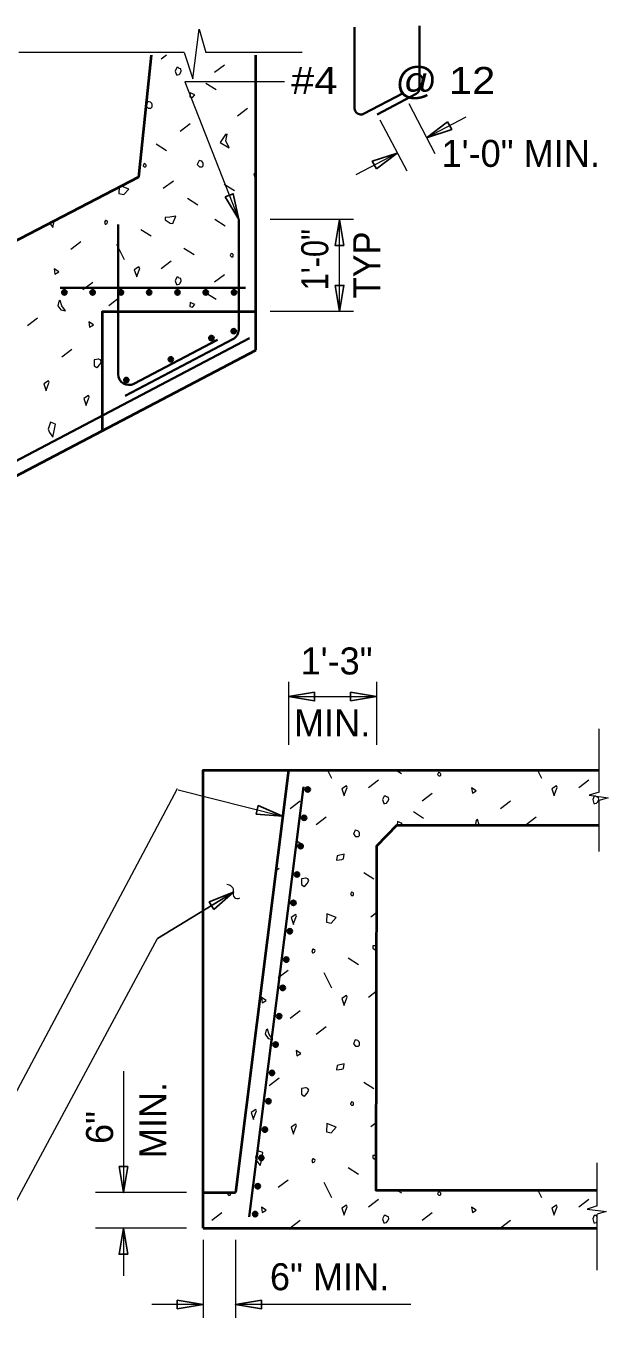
# Model space of a CAD drawing. Extents: x 0 to 22.7, y 0 to 15.6.
# Drawn here: x 6.629 to 8.87, y 5.449 to 10.444 of the extents above; entities that cross this region are included whole.
import ezdxf
from ezdxf.enums import TextEntityAlignment as Align

# ---------------------------------------------------------------- set-up
doc = ezdxf.new("R2010")
doc.units = 0
doc.header["$LTSCALE"] = 0.042
for name, color, linetype, lineweight in [('1', 7, 'Continuous', 13), ('3', 7, 'Continuous', 35), ('4', 7, 'Continuous', 13), ('7', 7, 'Continuous', 13)]:
    doc.layers.add(name, color=color, linetype=linetype, lineweight=lineweight)

msp = doc.modelspace()

# ---------------------------------------------------------------- linework, layer by layer
at = {"layer": '1'}
for p, q in [((7.23859, 10.3412), (6.60214, 10.3412)), ((7.69302, 10.3412), (7.32229, 10.3412)), ((8.83552, 7.49188), (8.83552, 7.73552)), ((8.83552, 7.26333), (8.83552, 7.45979)), ((8.82766, 5.89724), (8.82766, 6.06318)), ((8.82766, 5.64901), (8.82766, 5.86521))]:
    msp.add_line(p, q, dxfattribs=at)
at = {"layer": '1', "lineweight": 40}
for p, q in [((7.11073, 10.33198), (7.06307, 9.8613)), ((7.51385, 9.19516), (7.51385, 10.33198)), ((7.06307, 9.8613), (6.14734, 9.38661)), ((6.14396, 8.47438), (7.51385, 9.19516)), ((7.64047, 7.57573), (7.43552, 5.94859)), ((8.05745, 7.36453), (8.83552, 7.36458)), ((7.31172, 5.94859), (7.43552, 5.94859)), ((7.31172, 5.81099), (8.82734, 5.81099))]:
    msp.add_line(p, q, dxfattribs=at)
at = {"layer": '1'}
for points in [[(7.23859, 10.3412), (7.27115, 10.24057), (7.29661, 10.43167), (7.32229, 10.3412)], [(8.83552, 7.49188), (8.79693, 7.47932), (8.87005, 7.46969), (8.83552, 7.45979)], [(8.82766, 5.89724), (8.78906, 5.88474), (8.86219, 5.8751), (8.82766, 5.86521)]]:
    msp.add_lwpolyline(points, dxfattribs=at)
at = {"layer": '1', "lineweight": 40}
for points in [[(6.92401, 8.88714), (6.92401, 9.34396), (7.51385, 9.34396)], [(7.31172, 5.81099), (7.31172, 7.57661), (8.83552, 7.57661)], [(8.05745, 7.36453), (7.97885, 7.28281), (7.97667, 5.95828), (8.82766, 5.95833)]]:
    msp.add_lwpolyline(points, dxfattribs=at)
at = {"layer": '3'}
for p, q in [((7.89438, 10.43938), (7.89438, 10.12646)), ((8.14411, 10.20302), (8.14411, 10.44417)), ((8.08135, 10.18552), (7.92911, 10.10547)), ((7.98078, 10.10276), (8.13156, 10.18198)), ((7.44818, 9.27396), (7.44818, 9.69792)), ((6.98396, 9.67896), (6.98396, 9.10219)), ((6.76094, 9.43484), (7.475, 9.43484)), ((6.14974, 8.53552), (7.49031, 9.24089)), ((7.01094, 9.0187), (7.42594, 9.23708)), ((7.04505, 9.06531), (7.3662, 9.23427)), ((7.69776, 7.5125), (7.48901, 5.85479))]:
    msp.add_line(p, q, dxfattribs=at)
for centre, radius in [((6.77707, 9.41733), 0.0089), ((6.77707, 9.41733), 0.00593), ((6.77707, 9.41733), 0.00297), ((6.88592, 9.41733), 0.0089), ((6.88592, 9.41733), 0.00593), ((6.88592, 9.41733), 0.00297), ((6.99478, 9.41733), 0.0089), ((6.99478, 9.41733), 0.00593), ((6.99478, 9.41733), 0.00297), ((7.10363, 9.41733), 0.0089), ((7.10363, 9.41733), 0.00593), ((7.10363, 9.41733), 0.00297), ((7.21249, 9.41733), 0.0089), ((7.21249, 9.41733), 0.00593), ((7.21249, 9.41733), 0.00297), ((7.32134, 9.41733), 0.0089), ((7.32134, 9.41733), 0.00593), ((7.32134, 9.41733), 0.00297), ((7.4302, 9.41733), 0.0089), ((7.4302, 9.41733), 0.00593), ((7.4302, 9.41733), 0.00297), ((7.34311, 9.24124), 0.0089), ((7.34311, 9.24124), 0.00593), ((7.34311, 9.24124), 0.00297), ((7.42884, 9.2679), 0.0089), ((7.42884, 9.2679), 0.00593), ((7.42884, 9.2679), 0.00297), ((7.18697, 9.15936), 0.0089), ((7.18697, 9.15936), 0.00593), ((7.18697, 9.15936), 0.00297), ((7.01561, 9.07936), 0.0089), ((7.01561, 9.07936), 0.00593), ((7.01561, 9.07936), 0.00297), ((7.71379, 7.50171), 0.0089), ((7.71379, 7.50171), 0.00593), ((7.71379, 7.50171), 0.00297), ((7.70004, 7.39249), 0.0089), ((7.70004, 7.39249), 0.00593), ((7.70004, 7.39249), 0.00297), ((7.68629, 7.28327), 0.0089), ((7.68629, 7.28327), 0.00593), ((7.68629, 7.28327), 0.00297), ((7.67254, 7.17405), 0.0089), ((7.67254, 7.17405), 0.00593), ((7.67254, 7.17405), 0.00297), ((7.65884, 7.06483), 0.0089), ((7.65884, 7.06483), 0.00593), ((7.65884, 7.06483), 0.00297), ((7.64509, 6.95561), 0.0089), ((7.64509, 6.95561), 0.00593), ((7.64509, 6.95561), 0.00297), ((7.63134, 6.84639), 0.0089), ((7.63134, 6.84639), 0.00593), ((7.63134, 6.84639), 0.00297), ((7.61764, 6.73718), 0.0089), ((7.61764, 6.73718), 0.00593), ((7.61764, 6.73718), 0.00297), ((7.60389, 6.62801), 0.0089), ((7.60389, 6.62801), 0.00593), ((7.60389, 6.62801), 0.00297), ((7.59014, 6.51879), 0.0089), ((7.59014, 6.51879), 0.00593), ((7.59014, 6.51879), 0.00297), ((7.57645, 6.40957), 0.0089), ((7.57645, 6.40957), 0.00593), ((7.57645, 6.40957), 0.00297), ((7.5627, 6.30035), 0.0089), ((7.5627, 6.30035), 0.00593), ((7.5627, 6.30035), 0.00297), ((7.54895, 6.19113), 0.0089), ((7.54895, 6.19113), 0.00593), ((7.54895, 6.19113), 0.00297), ((7.53525, 6.08192), 0.0089), ((7.53525, 6.08192), 0.00593), ((7.53525, 6.08192), 0.00297), ((7.5215, 5.9727), 0.0089), ((7.5215, 5.9727), 0.00593), ((7.5215, 5.9727), 0.00297), ((7.51155, 5.86556), 0.0089), ((7.51155, 5.86556), 0.00593), ((7.51155, 5.86556), 0.00297)]:
    msp.add_circle(centre, radius, dxfattribs=at)
for centre, radius, start, end in [((8.12044, 10.20304), 0.0237, 297.75329, 0), ((7.91807, 10.12645), 0.0237, 180, 297.75192), ((7.91807, 10.12645), 0.0237, 180, 297.75192), ((7.40651, 9.27396), 0.04167, 297.75329, 0), ((7.02563, 9.10218), 0.04167, 180, 297.75192)]:
    msp.add_arc(centre, radius, start, end, dxfattribs=at)
at = {"layer": '4'}
for p, q in [((8.10281, 10.14469), (8.20354, 9.95297)), ((8.32234, 10.0925), (8.17177, 10.01344)), ((7.9913, 10.08271), (8.09484, 9.88563)), ((8.05885, 9.95417), (7.89938, 9.87042)), ((7.89063, 9.69792), (7.56984, 9.69792)), ((7.8363, 9.34396), (7.8363, 9.69792)), ((7.89063, 9.34396), (7.56984, 9.34396)), ((7.64047, 7.91599), (7.64047, 7.67328)), ((7.97885, 7.91599), (7.97885, 7.67328)), ((7.64047, 7.85974), (7.97885, 7.85974)), ((6.36161, 5.9025), (7.21276, 7.50573)), ((7.21495, 7.50063), (7.61646, 7.3987)), ((7.42859, 7.10609), (7.13583, 6.92714)), ((7.13583, 6.92714), (7.42859, 7.10609)), ((6.33057, 5.43), (7.13583, 6.92714)), ((7.00448, 6.41635), (7.00448, 5.94859)), ((7.24781, 5.94859), (6.89677, 5.94859)), ((7.24781, 5.81099), (6.89677, 5.81099)), ((7.00448, 5.81099), (7.00448, 5.62786)), ((7.31172, 5.76641), (7.31172, 5.46568)), ((7.43552, 5.76641), (7.43552, 5.46568)), ((7.31172, 5.51682), (7.11443, 5.51682)), ((8.11146, 5.51682), (7.43552, 5.51682))]:
    msp.add_line(p, q, dxfattribs=at)
msp.add_lwpolyline([(7.62406, 10.22911), (7.2413, 10.22911), (7.44818, 9.69792)], dxfattribs=at)
at = {"layer": '4', "lineweight": 25}
for points in [[(8.25255, 10.07469), (8.26807, 10.04516), (8.17177, 10.01344)], [(7.97807, 9.89292), (7.96255, 9.92245), (8.05885, 9.95417)], [(7.39635, 9.78505), (7.4274, 9.79714), (7.44818, 9.69792)], [(7.85297, 9.59792), (7.81964, 9.59792), (7.8363, 9.69792)], [(7.81964, 9.44396), (7.85297, 9.44396), (7.8363, 9.34396)], [(7.74047, 7.87641), (7.74047, 7.84307), (7.64047, 7.85974)], [(7.87885, 7.84307), (7.87885, 7.87641), (7.97885, 7.85974)], [(7.51542, 7.40714), (7.52365, 7.43948), (7.61646, 7.3987)], [(7.35198, 7.03974), (7.33458, 7.06818), (7.42859, 7.10609)], [(6.98781, 6.04859), (7.02115, 6.04859), (7.00448, 5.94859)], [(7.02115, 5.71099), (6.98781, 5.71099), (7.00448, 5.81099)], [(7.21172, 5.50016), (7.21172, 5.53349), (7.31172, 5.51682)], [(7.53552, 5.53349), (7.53552, 5.50016), (7.43552, 5.51682)]]:
    msp.add_lwpolyline(points, close=True, dxfattribs=at)
at = {"layer": '4'}
for centre, radius, start, end in [((7.4031, 7.10937), 0.0257, 352.67535, 92.38286), ((7.44329, 7.09799), 0.01679, 151.12288, 301.99449)]:
    msp.add_arc(centre, radius, start, end, dxfattribs=at)
at = {"layer": '7'}
for p, q in [((7.17073, 10.33198), (7.14979, 10.31604)), ((7.39406, 10.29339), (7.35557, 10.26406)), ((7.32214, 10.22411), (7.36172, 10.19911)), ((7.48234, 10.12615), (7.44385, 10.09682)), ((7.26141, 10.06635), (7.22292, 10.03708)), ((7.13099, 9.98948), (7.17063, 9.96453)), ((7.19656, 9.84656), (7.15802, 9.81729)), ((7.51385, 9.8776), (7.50656, 9.87281)), ((7.50656, 9.87281), (7.51385, 9.85156)), ((7.39255, 9.83464), (7.43208, 9.80979)), ((7.25167, 9.78), (7.2913, 9.755)), ((7.35661, 9.69943), (7.39615, 9.67438)), ((7.07156, 9.66016), (7.11115, 9.63516)), ((6.84031, 9.6124), (6.80182, 9.58313)), ((6.9776, 9.60354), (7.00693, 9.54469)), ((7.23667, 9.58792), (7.27625, 9.56292)), ((7.18828, 9.5374), (7.14979, 9.50813)), ((6.88698, 9.45589), (6.84849, 9.42656)), ((7.39406, 9.48542), (7.35557, 9.45615)), ((6.98641, 9.39464), (6.94792, 9.36531)), ((7.32214, 9.41615), (7.36172, 9.39115)), ((7.0987, 9.345), (7.09823, 9.34396)), ((7.1024, 9.34396), (7.0987, 9.345)), ((6.67354, 9.31818), (6.63505, 9.28885)), ((6.80557, 9.19724), (6.76708, 9.16792)), ((7.78995, 7.57583), (7.80531, 7.54505)), ((8.05438, 7.57604), (8.07464, 7.56323)), ((8.59844, 7.57646), (8.61411, 7.54505)), ((7.98667, 7.53771), (7.94818, 7.50844)), ((8.79547, 7.53771), (8.75698, 7.50844)), ((7.68536, 7.4562), (7.64688, 7.42693)), ((8.19245, 7.48573), (8.15396, 7.45646)), ((8.49417, 7.4562), (8.45568, 7.42693)), ((7.78479, 7.39495), (7.7463, 7.36568)), ((8.12052, 7.41651), (8.1601, 7.39151)), ((8.59359, 7.39495), (8.5551, 7.36568)), ((8.05943, 7.37859), (8.0588, 7.36453)), ((7.60396, 7.19755), (7.59167, 7.18818)), ((7.92938, 7.18182), (7.96901, 7.15688)), ((7.97844, 7.02635), (7.95641, 7.00964)), ((7.86995, 6.8525), (7.90953, 6.8275)), ((7.6387, 6.80479), (7.60021, 6.77547)), ((7.77599, 6.79589), (7.80531, 6.73708)), ((7.97792, 6.72307), (7.94818, 6.70047)), ((7.68536, 6.64823), (7.64688, 6.61896)), ((7.78479, 6.58698), (7.7463, 6.55771)), ((7.60396, 6.38958), (7.56547, 6.36031)), ((7.92938, 6.37391), (7.96901, 6.34891)), ((7.97708, 6.2174), (7.95641, 6.20167)), ((7.86995, 6.04453), (7.90953, 6.01953)), ((7.6387, 5.99682), (7.60021, 5.96755)), ((7.77599, 5.98797), (7.80531, 5.92911)), ((8.05729, 5.95828), (8.07464, 5.94734)), ((8.59953, 5.95833), (8.61411, 5.92911)), ((7.98667, 5.92182), (7.94818, 5.8925)), ((8.79547, 5.92182), (8.75698, 5.8925)), ((7.38365, 5.86984), (7.34516, 5.84052)), ((8.19245, 5.86984), (8.15396, 5.84052)), ((7.68536, 5.84026), (7.64688, 5.81099)), ((8.49417, 5.84026), (8.45568, 5.81099))]:
    msp.add_line(p, q, dxfattribs=at)
for points in [[(7.2037, 10.27031), (7.20833, 10.25552), (7.2126, 10.25552), (7.21859, 10.25698), (7.22292, 10.2613), (7.22724, 10.27031), (7.22604, 10.27906), (7.21859, 10.28057), (7.21547, 10.28365), (7.20958, 10.28365)], [(7.0987, 10.15292), (7.0913, 10.13677), (7.09995, 10.12776), (7.11052, 10.12776), (7.1149, 10.1325), (7.1149, 10.14109), (7.11344, 10.14536), (7.10885, 10.1501)], [(7.26104, 10.18625), (7.26036, 10.17042), (7.2699, 10.16818), (7.27911, 10.17885)], [(7.39703, 10.02552), (7.37646, 9.99469), (7.41109, 9.97396), (7.39844, 10.00198), (7.40375, 10.02766)], [(7.08396, 9.91344), (7.08026, 9.90536), (7.08458, 9.90083), (7.0899, 9.90083), (7.09203, 9.90323), (7.09203, 9.9075), (7.0913, 9.90969), (7.08901, 9.91203)], [(7.29552, 9.92594), (7.28813, 9.90979), (7.29677, 9.90078), (7.3074, 9.90078), (7.31172, 9.90552), (7.31172, 9.91411), (7.31026, 9.91839), (7.30568, 9.92313)], [(6.93198, 9.68755), (6.93432, 9.68016), (6.93646, 9.68016), (6.93943, 9.68089), (6.94161, 9.68302), (6.94375, 9.68755), (6.94313, 9.69193), (6.93943, 9.69271), (6.93786, 9.69422), (6.93495, 9.69422)], [(7.18339, 9.70776), (7.16573, 9.70625), (7.16573, 9.69745), (7.1849, 9.68422), (7.19526, 9.68271), (7.20557, 9.71073)], [(7.41922, 9.56703), (7.41552, 9.55891), (7.41984, 9.55443), (7.42516, 9.55443), (7.42734, 9.55677), (7.42734, 9.56109), (7.42661, 9.56323), (7.42432, 9.56563)], [(6.73755, 9.50802), (6.74052, 9.48734), (6.75531, 9.49625)], [(7.04641, 9.5037), (7.05552, 9.47708), (7.05552, 9.48), (7.06729, 9.50958), (7.06427, 9.51547)], [(7.2037, 9.46234), (7.20833, 9.4476), (7.2126, 9.4476), (7.21859, 9.44906), (7.22292, 9.45333), (7.22724, 9.46234), (7.22604, 9.47109), (7.21859, 9.4726), (7.21547, 9.47568), (7.20958, 9.47568)], [(6.75552, 9.38266), (6.75229, 9.36604), (6.76328, 9.34984), (6.78172, 9.3462), (6.76698, 9.36573), (6.76068, 9.38594)], [(7.26104, 9.37828), (7.26036, 9.36245), (7.2699, 9.36021), (7.27911, 9.37094)], [(6.87083, 9.30344), (6.87385, 9.28281), (6.88865, 9.29167)], [(6.89214, 9.15698), (6.89214, 9.13469), (6.90224, 9.1275), (6.90531, 9.13036), (6.91401, 9.13927), (6.9199, 9.15109), (6.91563, 9.15698), (6.90969, 9.15984), (6.90682, 9.15984), (6.90104, 9.15823)], [(6.69776, 9.06484), (6.70688, 9.03828), (6.70688, 9.04115), (6.7187, 9.07073), (6.71568, 9.07661)], [(6.85151, 9.00828), (6.86063, 8.98172), (6.86063, 8.98458), (6.8724, 9.01417), (6.86943, 9.02005)], [(6.72365, 8.9174), (6.71469, 8.89083), (6.71927, 8.8776), (6.7325, 8.8599), (6.73833, 8.88349), (6.74281, 8.91005)], [(8.2176, 7.56734), (8.21391, 7.55922), (8.21823, 7.55474), (8.22354, 7.55474), (8.22573, 7.55708), (8.22573, 7.56141), (8.225, 7.56354), (8.22271, 7.56594)], [(7.84479, 7.50401), (7.85391, 7.47745), (7.85391, 7.48031), (7.86568, 7.5099), (7.86266, 7.51578)], [(8.34474, 7.50833), (8.34771, 7.48766), (8.3625, 7.49656)], [(8.65359, 7.50401), (8.66271, 7.47745), (8.66271, 7.48031), (8.67448, 7.5099), (8.67146, 7.51578)], [(8.00208, 7.46266), (8.00672, 7.44792), (8.01099, 7.44792), (8.01698, 7.44938), (8.0213, 7.45365), (8.02562, 7.46266), (8.02443, 7.47141), (8.01698, 7.47297), (8.01385, 7.47599), (8.00797, 7.47599)], [(8.81089, 7.46266), (8.81552, 7.44792), (8.81979, 7.44792), (8.82578, 7.44938), (8.8301, 7.45365), (8.83443, 7.46266), (8.83318, 7.47141), (8.82578, 7.47297), (8.82266, 7.47599), (8.81677, 7.47599)], [(7.89708, 7.34531), (7.88969, 7.32911), (7.89833, 7.32016), (7.90891, 7.32016), (7.91328, 7.32484), (7.91328, 7.33349), (7.91182, 7.33771), (7.90724, 7.34245)], [(7.66922, 7.30375), (7.67224, 7.28313), (7.68703, 7.29198)], [(7.8275, 7.24646), (7.82453, 7.2288), (7.84521, 7.23177), (7.85104, 7.23464), (7.85401, 7.25234)], [(7.69052, 7.15734), (7.69052, 7.135), (7.70063, 7.12781), (7.7037, 7.13068), (7.7124, 7.13958), (7.71828, 7.15141), (7.71401, 7.15734), (7.70807, 7.16016), (7.70521, 7.16016), (7.69943, 7.15854)], [(7.88234, 7.10583), (7.87865, 7.09771), (7.88297, 7.09323), (7.88828, 7.09323), (7.89042, 7.09557), (7.89042, 7.0999), (7.88969, 7.10203), (7.8874, 7.10438)], [(7.6499, 7.00859), (7.65901, 6.98203), (7.65901, 6.9849), (7.67078, 7.01453), (7.66781, 7.02036)], [(7.78698, 7.02266), (7.78557, 6.99099), (7.80469, 6.98656), (7.82307, 7.00792)], [(7.73036, 6.8799), (7.73271, 6.8725), (7.73484, 6.8725), (7.73781, 6.87328), (7.74, 6.87542), (7.74214, 6.8799), (7.74151, 6.88432), (7.73781, 6.88505), (7.73625, 6.88661), (7.73333, 6.88661)], [(7.53594, 6.70036), (7.53891, 6.67974), (7.5537, 6.68859)], [(7.84479, 6.69609), (7.85391, 6.66948), (7.85391, 6.67234), (7.86568, 6.70193), (7.86266, 6.70781)], [(7.55391, 6.57505), (7.55068, 6.55844), (7.56167, 6.54219), (7.5801, 6.53854), (7.56536, 6.55807), (7.55906, 6.57833)], [(7.66922, 6.49578), (7.67224, 6.47516), (7.68703, 6.48401)], [(7.89708, 6.53734), (7.88969, 6.5212), (7.89833, 6.51219), (7.90891, 6.51219), (7.91328, 6.51688), (7.91328, 6.52552), (7.91182, 6.52974), (7.90724, 6.53453)], [(7.8275, 6.43849), (7.82453, 6.42083), (7.84521, 6.4238), (7.85104, 6.42672), (7.85401, 6.44438)], [(7.69052, 6.34938), (7.69052, 6.32703), (7.70063, 6.31984), (7.7037, 6.32276), (7.7124, 6.33161), (7.71828, 6.34344), (7.71401, 6.34938), (7.70807, 6.35219), (7.70521, 6.35219), (7.69943, 6.35057)], [(7.88234, 6.29786), (7.87865, 6.28974), (7.88297, 6.28526), (7.88828, 6.28526), (7.89042, 6.2876), (7.89042, 6.29193), (7.88969, 6.29406), (7.8874, 6.29641)], [(7.49615, 6.25724), (7.50526, 6.23063), (7.50526, 6.23349), (7.51708, 6.26307), (7.51406, 6.26896)], [(7.6499, 6.20068), (7.65901, 6.17411), (7.65901, 6.17693), (7.67078, 6.20656), (7.66781, 6.21245)], [(7.78698, 6.21474), (7.78557, 6.18307), (7.80469, 6.17859), (7.82307, 6.19995)], [(7.52203, 6.10974), (7.51307, 6.08323), (7.51766, 6.06995), (7.53089, 6.05224), (7.53672, 6.07583), (7.5412, 6.1024)], [(7.73036, 6.07193), (7.73271, 6.06453), (7.73484, 6.06453), (7.73781, 6.06531), (7.74, 6.06745), (7.74214, 6.07193), (7.74151, 6.07635), (7.73781, 6.07708), (7.73625, 6.07865), (7.73333, 6.07865)], [(8.2176, 5.95141), (8.21391, 5.94333), (8.21823, 5.9388), (8.22354, 5.9388), (8.22573, 5.9412), (8.22573, 5.94552), (8.225, 5.94766), (8.22271, 5.95)], [(7.84479, 5.88813), (7.85391, 5.86151), (7.85391, 5.86438), (7.86568, 5.89401), (7.86266, 5.89984)], [(8.65359, 5.88813), (8.66271, 5.86151), (8.66271, 5.86438), (8.67448, 5.89401), (8.67146, 5.89984)], [(7.53594, 5.89245), (7.53891, 5.87177), (7.5537, 5.88068)], [(8.00208, 5.84672), (8.00672, 5.83198), (8.01099, 5.83198), (8.01698, 5.83344), (8.0213, 5.83776), (8.02562, 5.84672), (8.02443, 5.85547), (8.01698, 5.85703), (8.01385, 5.86005), (8.00797, 5.86005)], [(8.34474, 5.89245), (8.34771, 5.87177), (8.3625, 5.88068)]]:
    msp.add_lwpolyline(points, close=True, dxfattribs=at)
for points in [[(6.98823, 9.8225), (6.98719, 9.79865), (7.0063, 9.79422), (7.02469, 9.81557), (6.99682, 9.82698)], [(6.72063, 9.6838), (6.7325, 9.66786), (6.73833, 9.69146), (6.73859, 9.69313)], [(8.07172, 7.36453), (8.0775, 7.37125), (8.05943, 7.37859)], [(8.36271, 7.38297), (8.35943, 7.36641), (8.36068, 7.36453)], [(8.37531, 7.36453), (8.37417, 7.36604), (8.36786, 7.3863), (8.36271, 7.38297)], [(7.97823, 6.89984), (7.96411, 6.89865), (7.96411, 6.88984), (7.97818, 6.8801)], [(7.97688, 6.09177), (7.96411, 6.09068), (7.96411, 6.08188), (7.97688, 6.07307)], [(7.4075, 5.94859), (7.4051, 5.94333), (7.40943, 5.9388), (7.41474, 5.9388), (7.41693, 5.9412), (7.41693, 5.94552), (7.4162, 5.94766), (7.41526, 5.94859)], [(8.82745, 5.85667), (8.82578, 5.85703), (8.82266, 5.86005), (8.81677, 5.86005), (8.81089, 5.84672)], [(8.81089, 5.84672), (8.81552, 5.83198), (8.81979, 5.83198), (8.82578, 5.83344), (8.8274, 5.83505)]]:
    msp.add_lwpolyline(points, dxfattribs=at)

# ---------------------------------------------------------------- texts
at = {"layer": '4', "width": 1.15}
msp.add_text('#4     @ 12', height=0.1041, dxfattribs=at).set_placement((7.65026, 10.18177))
at = {"layer": '4'}
for s, p in [('1\'-0" MIN.', (8.22911, 9.90089)), ('6" MIN.', (7.56839, 5.57208))]:
    msp.add_text(s, height=0.1041, dxfattribs=at).set_placement(p)
for s, width, p in [('1\'-0"', 0.85, (7.79307, 9.42552)), ('TYP', 0.95, (7.99318, 9.39453))]:
    msp.add_text(s, height=0.1042, rotation=90, dxfattribs=dict(at, width=width)).set_placement(p)
for s, p in [('1\'-3"', (7.8249, 7.94495)), ('MIN.', (7.80781, 7.70604))]:
    msp.add_text(s, height=0.1041, dxfattribs=at).set_placement(p, align=Align.CENTER)
for s, p in [('MIN.', (7.1699, 6.08078)), ('6"', (6.96458, 6.13563))]:
    msp.add_text(s, height=0.1041, rotation=90, dxfattribs=at).set_placement(p)

doc.saveas('drawing.dxf')
